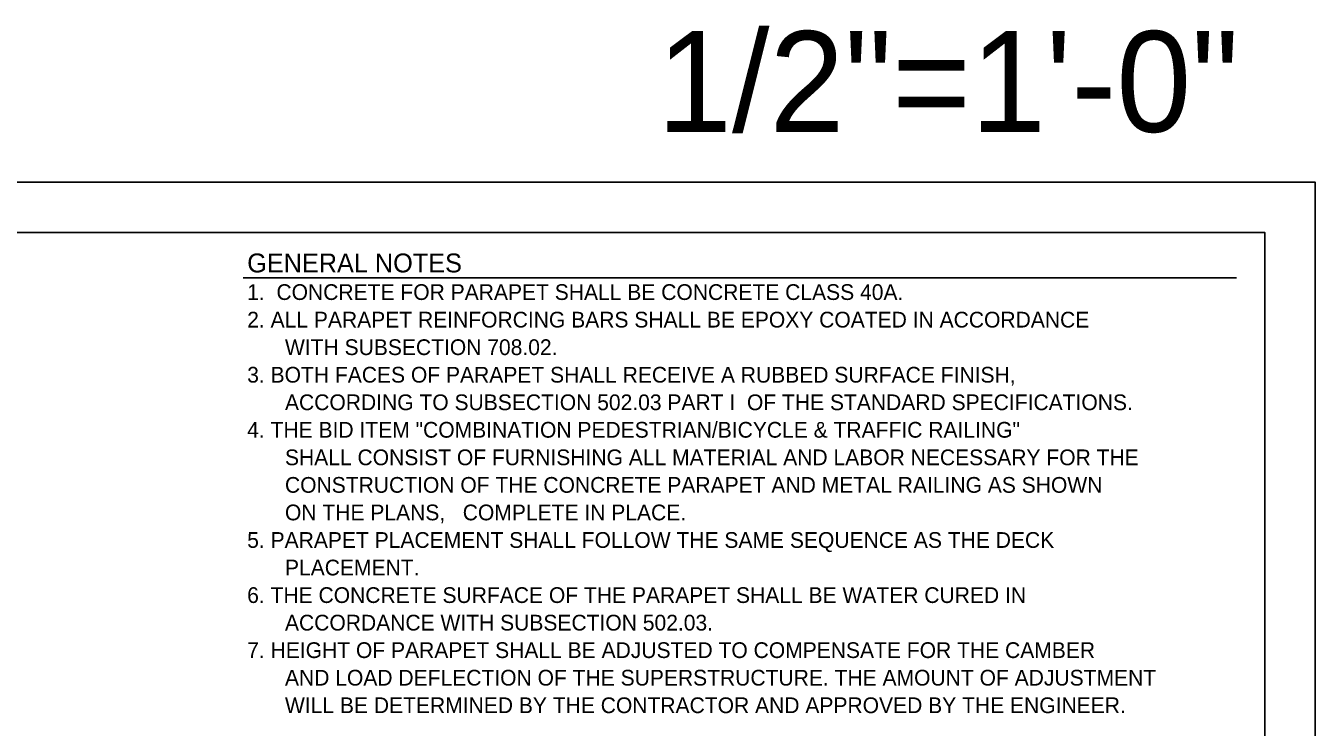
# Model space of a CAD drawing. Extents: x 0 to 68, y 0 to 47.1.
# Drawn here: x 42.4 to 68, y 33.18 to 47.11 of the extents above; entities that cross this region are included whole.
import ezdxf

# ---------------------------------------------------------------- set-up
doc = ezdxf.new("R2010")
doc.units = 0
for name, color, linetype in [('BORDER_ANNO_Cutsheet', 7, 'Continuous'), ('BRDG_ANNO_Anno-Sheet', 7, 'Continuous'), ('BRDG_ANNO_General-Notes', 7, 'Continuous')]:
    doc.layers.add(name, color=color, linetype=linetype)

msp = doc.modelspace()

# ---------------------------------------------------------------- linework, layer by layer
at = {"layer": 'BORDER_ANNO_Cutsheet'}
msp.add_lwpolyline([(0, 44), (68, 44), (68, 0), (0, 0)], close=True, dxfattribs=at)
at = {"layer": 'BRDG_ANNO_Anno-Sheet'}
msp.add_lwpolyline([(3, 43), (67, 43), (67, 1), (3, 1)], close=True, dxfattribs=at)
at = {"layer": 'BRDG_ANNO_General-Notes'}
msp.add_line((46.716, 42.1), (66.439, 42.1), dxfattribs=at)

# ---------------------------------------------------------------- texts
at = {"layer": 'BRDG_ANNO_Anno-Sheet'}
msp.add_text('1/2"=1\'-0"', height=2, dxfattribs=at).set_placement((54.934, 45))
at = {"layer": 'BRDG_ANNO_General-Notes'}
for s, height, p in [('GENERAL NOTES', 0.375, (46.795, 42.21)), ('1.  CONCRETE FOR PARAPET SHALL BE CONCRETE CLASS 40A.', 0.3125, (46.795, 41.663)), ('2. ALL PARAPET REINFORCING BARS SHALL BE EPOXY COATED IN ACCORDANCE', 0.3125, (46.795, 41.116)), ('WITH SUBSECTION 708.02.', 0.3125, (47.545, 40.569)), ('3. BOTH FACES OF PARAPET SHALL RECEIVE A RUBBED SURFACE FINISH,  ', 0.3125, (46.795, 40.022)), ('ACCORDING TO SUBSECTION 502.03 PART I  OF THE STANDARD SPECIFICATIONS.', 0.3125, (47.545, 39.475)), ('4. THE BID ITEM "COMBINATION PEDESTRIAN/BICYCLE & TRAFFIC RAILING"', 0.3125, (46.795, 38.929)), ('SHALL CONSIST OF FURNISHING ALL MATERIAL AND LABOR NECESSARY FOR THE', 0.3125, (47.545, 38.382)), ('CONSTRUCTION OF THE CONCRETE PARAPET AND METAL RAILING AS SHOWN', 0.3125, (47.545, 37.835)), ('ON THE PLANS,   COMPLETE IN PLACE.', 0.3125, (47.545, 37.288)), ('5. PARAPET PLACEMENT SHALL FOLLOW THE SAME SEQUENCE AS THE DECK', 0.3125, (46.795, 36.741)), ('PLACEMENT.', 0.3125, (47.545, 36.194)), ('6. THE CONCRETE SURFACE OF THE PARAPET SHALL BE WATER CURED IN', 0.3125, (46.795, 35.647)), ('ACCORDANCE WITH SUBSECTION 502.03.', 0.3125, (47.545, 35.1)), ('7. HEIGHT OF PARAPET SHALL BE ADJUSTED TO COMPENSATE FOR THE CAMBER', 0.3125, (46.795, 34.554)), ('AND LOAD DEFLECTION OF THE SUPERSTRUCTURE. THE AMOUNT OF ADJUSTMENT', 0.3125, (47.545, 34.007)), ('WILL BE DETERMINED BY THE CONTRACTOR AND APPROVED BY THE ENGINEER.', 0.3125, (47.545, 33.46))]:
    msp.add_text(s, height=height, dxfattribs=at).set_placement(p)

doc.saveas('drawing.dxf')
